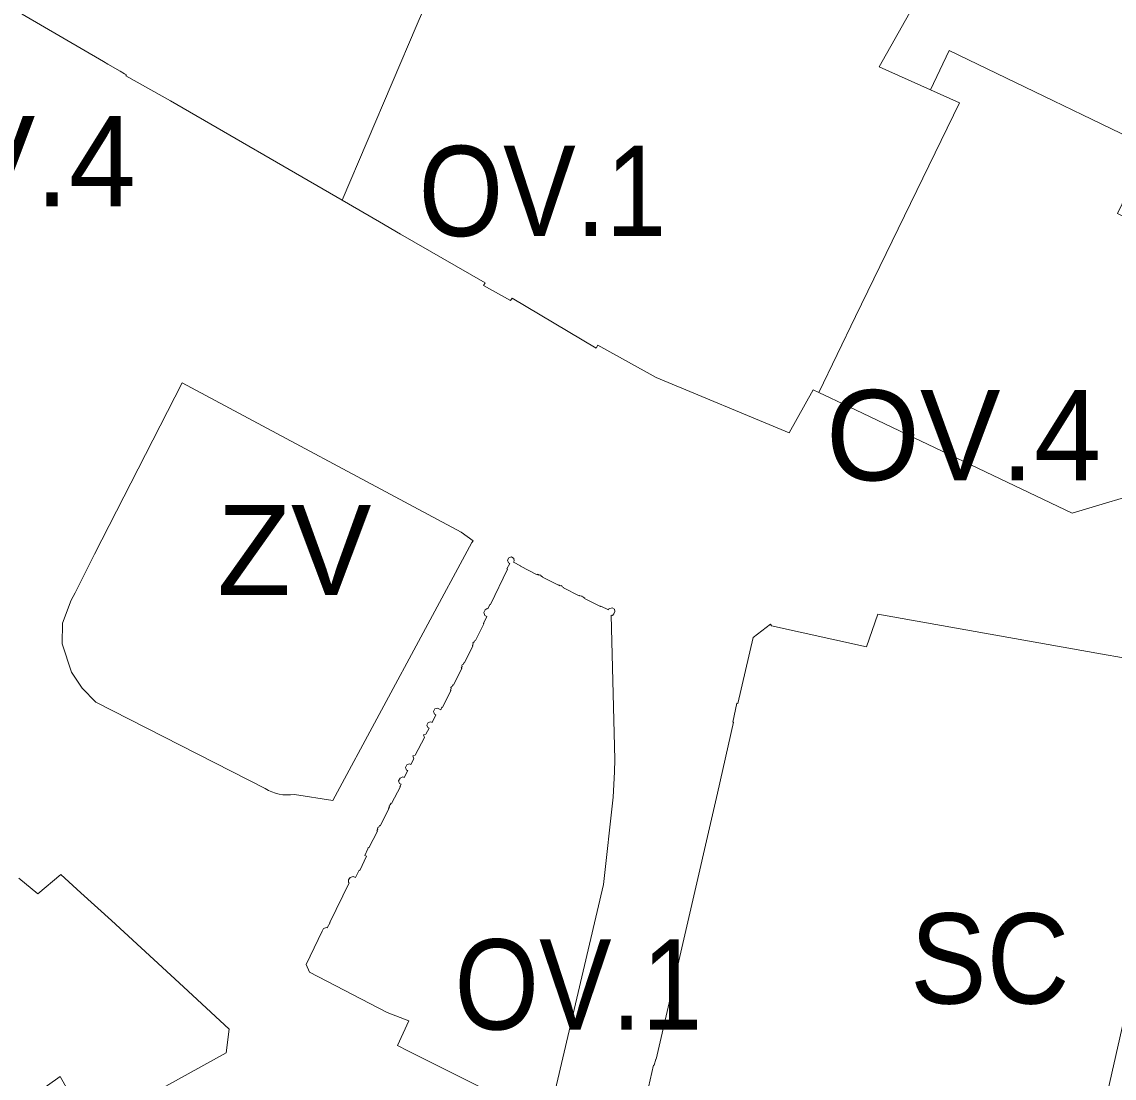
# Model space of a CAD drawing. Extents: x -650451 to -642268, y -1075216 to -1066610.
# Drawn here: x -647013.1 to -646868, y -1070712 to -1070571.6 of the extents above; entities that cross this region are included whole.
import ezdxf

# ---------------------------------------------------------------- set-up
doc = ezdxf.new("R2010")
doc.units = 0
doc.header["$LTSCALE"] = 4.8
for name, color, linetype, lineweight in [('11', 7, 'Continuous', 13), ('12', 7, 'Continuous', 13), ('15', 7, 'Continuous', 13), ('17', 7, 'Continuous', 13), ('40', 7, 'Continuous', 13)]:
    doc.layers.add(name, color=color, linetype=linetype, lineweight=lineweight)
doc.layers.add('62', color=7, linetype='Continuous')

msp = doc.modelspace()

# ---------------------------------------------------------------- linework, layer by layer
at = {"layer": '11'}
for points in [[(-646970.59, -1070595.31), (-646993.39, -1070582.12), (-646999.31, -1070578.78), (-646999.24, -1070578.67), (-646999.5, -1070578.52), (-647000.08, -1070578.18), (-647001.71, -1070577.23), (-647002.29, -1070576.9), (-647013.1, -1070570.62), (-647005.65, -1070557.68), (-647005.56, -1070557.72), (-647005.3, -1070557.33), (-646999.98, -1070548.21), (-646991.63, -1070534.15)], [(-646886.721, -1070555.37), (-646891.65, -1070564.15), (-646899.2, -1070577.61), (-646892.4, -1070580.64)], [(-646954.38, -1070557.43), (-646960.59, -1070571.95), (-646970.59, -1070595.31)], [(-646970.59, -1070595.31), (-646960.59, -1070571.95), (-646954.38, -1070557.43)], [(-646892.4, -1070580.64), (-646889.9, -1070575.41), (-646876.02, -1070582.12), (-646872.19, -1070583.97), (-646863.26, -1070588.3), (-646867.54, -1070597.11), (-646865.02, -1070598.34), (-646859.48, -1070601.1), (-646852.3, -1070604.63), (-646849.7, -1070605.93), (-646848.99, -1070606.28), (-646849.59, -1070607.4)], [(-646892.4, -1070580.64), (-646888.51, -1070582.38), (-646902.34, -1070610.8), (-646907.24, -1070620.87)], [(-646907.24, -1070620.87), (-646902.34, -1070610.8), (-646888.51, -1070582.38), (-646892.4, -1070580.64)], [(-646907.24, -1070620.87), (-646907.97, -1070620.52), (-646911.17, -1070626.24), (-646928.86, -1070618.91), (-646936.61, -1070614.62), (-646936.83, -1070615.01), (-646948, -1070608.33), (-646948.18, -1070608.65), (-646951.78, -1070606.66), (-646951.58, -1070606.31), (-646962.81, -1070599.83), (-646965.61, -1070598.2), (-646970.59, -1070595.31)], [(-646849.59, -1070607.4), (-646854.09, -1070615.86), (-646855.52, -1070618.54), (-646862.62, -1070633.65), (-646873.54, -1070636.92), (-646903.29, -1070622.75), (-646907.24, -1070620.87)], [(-646961.46, -1070670.34), (-646961.06, -1070669.57), (-646961.16, -1070669.2), (-646960.85, -1070669.1), (-646959.65, -1070666.76), (-646959.76, -1070666.41), (-646959.44, -1070666.32), (-646959.01, -1070665.52), (-646959.19, -1070665.43), (-646959.31, -1070665.1), (-646959.14, -1070664.75), (-646958.79, -1070664.66), (-646958.63, -1070664.74), (-646958.14, -1070663.73), (-646958.3, -1070663.65), (-646958.42, -1070663.31), (-646958.25, -1070662.96), (-646957.89, -1070662.84), (-646957.48, -1070663.05), (-646957.31, -1070662.71), (-646957.25, -1070662.74), (-646956.13, -1070660.48), (-646956.19, -1070660.45), (-646956.08, -1070660.22), (-646956.12, -1070660.12), (-646956.06, -1070660.01), (-646955.96, -1070659.97), (-646955.85, -1070659.76), (-646955.79, -1070659.79), (-646954.68, -1070657.55), (-646954.74, -1070657.52), (-646954.63, -1070657.29), (-646954.66, -1070657.19), (-646954.61, -1070657.08), (-646954.5, -1070657.04), (-646954.39, -1070656.81), (-646954.33, -1070656.84), (-646953.2, -1070654.57), (-646953.26, -1070654.53), (-646953.15, -1070654.31), (-646953.19, -1070654.2), (-646953.13, -1070654.09), (-646953.03, -1070654.06), (-646952.91, -1070653.83), (-646952.85, -1070653.87), (-646951.75, -1070651.64), (-646951.81, -1070651.6), (-646951.34, -1070650.65), (-646951.61, -1070650.52), (-646951.73, -1070650.14), (-646951.57, -1070649.76), (-646951.28, -1070649.62), (-646951.23, -1070649.65), (-646950.94, -1070649.06), (-646950.88, -1070649.09), (-646948.6, -1070644.37), (-646948.67, -1070644.34), (-646948.31, -1070643.61), (-646948.47, -1070643.54), (-646948.58, -1070643.18), (-646948.41, -1070642.85), (-646948.07, -1070642.74), (-646947.76, -1070642.97), (-646947.72, -1070643.27), (-646947.79, -1070643.45), (-646946.85, -1070643.93), (-646946.88, -1070643.99), (-646944.65, -1070645.11), (-646944.62, -1070645.05), (-646944.41, -1070645.15), (-646944.3, -1070645.12), (-646944.19, -1070645.17), (-646944.16, -1070645.28), (-646943.93, -1070645.39), (-646943.96, -1070645.45), (-646941.84, -1070646.52), (-646941.81, -1070646.46), (-646941.59, -1070646.57), (-646941.48, -1070646.53), (-646941.38, -1070646.59), (-646941.34, -1070646.7), (-646941.12, -1070646.81), (-646941.15, -1070646.87), (-646939.06, -1070647.92), (-646939.03, -1070647.86), (-646938.8, -1070647.98), (-646938.69, -1070647.94), (-646938.58, -1070648), (-646938.55, -1070648.1), (-646938.32, -1070648.22), (-646938.35, -1070648.28), (-646936.24, -1070649.34), (-646936.21, -1070649.28), (-646935.19, -1070649.79), (-646935.12, -1070649.63), (-646934.71, -1070649.53), (-646934.39, -1070649.68), (-646934.32, -1070650), (-646934.48, -1070650.33), (-646934.66, -1070650.55), (-646934.82, -1070650.48)], [(-646934.82, -1070650.48), (-646934.35, -1070669.69), (-646934.36, -1070671.33), (-646934.56, -1070674.69), (-646935.85, -1070686.31), (-646943.1, -1070717.25)], [(-646951.12, -1070713.75), (-646955.71, -1070711.45), (-646961.85, -1070708.38), (-646963.2, -1070707.7), (-646961.71, -1070704.43), (-646964.61, -1070703.3), (-646974.92, -1070697.94), (-646975.35, -1070696.93), (-646973.25, -1070692.48), (-646973.07, -1070692.12), (-646972.67, -1070691.99), (-646972.57, -1070692.04), (-646972.16, -1070691.35), (-646972.22, -1070691.32), (-646969.63, -1070686.07), (-646969.71, -1070686.03), (-646969.74, -1070685.68), (-646969.53, -1070685.37), (-646969.11, -1070685.22), (-646968.79, -1070685.37), (-646968.3, -1070684.38), (-646968.23, -1070684.41), (-646967.36, -1070682.51), (-646967.54, -1070682.42), (-646967.18, -1070681.53), (-646967.11, -1070681.38), (-646967.05, -1070681.42), (-646965.89, -1070679.18), (-646965.95, -1070679.15), (-646965.84, -1070678.92), (-646965.87, -1070678.82), (-646965.82, -1070678.71), (-646965.71, -1070678.67), (-646965.59, -1070678.44), (-646965.53, -1070678.48), (-646964.36, -1070676.21), (-646964.42, -1070676.18), (-646964.3, -1070675.96), (-646964.34, -1070675.85), (-646964.28, -1070675.74), (-646964.18, -1070675.71), (-646964.06, -1070675.49), (-646964, -1070675.52), (-646962.84, -1070673.28), (-646962.9, -1070673.25), (-646962.75, -1070672.95), (-646962.95, -1070672.85), (-646963.07, -1070672.49), (-646962.87, -1070672.15), (-646962.49, -1070671.99), (-646962.32, -1070672.07), (-646961.86, -1070671.15), (-646962.03, -1070671.07), (-646962.15, -1070670.72), (-646961.98, -1070670.37), (-646961.62, -1070670.26), (-646961.46, -1070670.34)]]:
    msp.add_lwpolyline(points, dxfattribs=at)
at = {"layer": '12'}
for points in [[(-646892.4, -1070580.64), (-646899.2, -1070577.61), (-646891.65, -1070564.15), (-646886.721, -1070555.37)], [(-646848.99, -1070606.28), (-646849.7, -1070605.93), (-646852.3, -1070604.63), (-646859.48, -1070601.1), (-646865.02, -1070598.34), (-646867.54, -1070597.11), (-646863.26, -1070588.3), (-646872.19, -1070583.97), (-646876.02, -1070582.12), (-646889.9, -1070575.41), (-646892.4, -1070580.64)]]:
    msp.add_lwpolyline(points, dxfattribs=at)
at = {"layer": '15'}
for points in [[(-646991.63, -1070534.15), (-646999.98, -1070548.21), (-647005.3, -1070557.33), (-647005.56, -1070557.72), (-647005.65, -1070557.68), (-647013.1, -1070570.62), (-647002.29, -1070576.9), (-647001.71, -1070577.23), (-647000.08, -1070578.18), (-646999.5, -1070578.52), (-646999.24, -1070578.67), (-646999.31, -1070578.78), (-646993.39, -1070582.12), (-646970.59, -1070595.31)], [(-646970.59, -1070595.31), (-646965.61, -1070598.2), (-646962.81, -1070599.83), (-646951.58, -1070606.31), (-646951.78, -1070606.66), (-646948.18, -1070608.65), (-646948, -1070608.33), (-646936.83, -1070615.01), (-646936.61, -1070614.62), (-646928.86, -1070618.91), (-646911.17, -1070626.24), (-646907.97, -1070620.52), (-646907.24, -1070620.87)], [(-646907.24, -1070620.87), (-646903.29, -1070622.75), (-646873.54, -1070636.92), (-646862.62, -1070633.65), (-646855.52, -1070618.54), (-646854.09, -1070615.86), (-646849.59, -1070607.4)], [(-646934.82, -1070650.48), (-646934.66, -1070650.55), (-646934.48, -1070650.33), (-646934.32, -1070650), (-646934.39, -1070649.68), (-646934.71, -1070649.53), (-646935.12, -1070649.63), (-646935.19, -1070649.79), (-646936.21, -1070649.28), (-646936.24, -1070649.34), (-646938.35, -1070648.28), (-646938.32, -1070648.22), (-646938.55, -1070648.1), (-646938.58, -1070648), (-646938.69, -1070647.94), (-646938.8, -1070647.98), (-646939.03, -1070647.86), (-646939.06, -1070647.92), (-646941.15, -1070646.87), (-646941.12, -1070646.81), (-646941.34, -1070646.7), (-646941.38, -1070646.59), (-646941.48, -1070646.53), (-646941.59, -1070646.57), (-646941.81, -1070646.46), (-646941.84, -1070646.52), (-646943.96, -1070645.45), (-646943.93, -1070645.39), (-646944.16, -1070645.28), (-646944.19, -1070645.17), (-646944.3, -1070645.12), (-646944.41, -1070645.15), (-646944.62, -1070645.05), (-646944.65, -1070645.11), (-646946.88, -1070643.99), (-646946.85, -1070643.93), (-646947.79, -1070643.45), (-646947.72, -1070643.27), (-646947.76, -1070642.97), (-646948.07, -1070642.74), (-646948.41, -1070642.85), (-646948.58, -1070643.18), (-646948.47, -1070643.54), (-646948.31, -1070643.61), (-646948.67, -1070644.34), (-646948.6, -1070644.37), (-646950.88, -1070649.09), (-646950.94, -1070649.06), (-646951.23, -1070649.65), (-646951.28, -1070649.62), (-646951.57, -1070649.76), (-646951.73, -1070650.14), (-646951.61, -1070650.52), (-646951.34, -1070650.65), (-646951.81, -1070651.6), (-646951.75, -1070651.64), (-646952.85, -1070653.87), (-646952.91, -1070653.83), (-646953.03, -1070654.06), (-646953.13, -1070654.09), (-646953.19, -1070654.2), (-646953.15, -1070654.31), (-646953.26, -1070654.53), (-646953.2, -1070654.57), (-646954.33, -1070656.84), (-646954.39, -1070656.81), (-646954.5, -1070657.04), (-646954.61, -1070657.08), (-646954.66, -1070657.19), (-646954.63, -1070657.29), (-646954.74, -1070657.52), (-646954.68, -1070657.55), (-646955.79, -1070659.79), (-646955.85, -1070659.76), (-646955.96, -1070659.97), (-646956.06, -1070660.01), (-646956.12, -1070660.12), (-646956.08, -1070660.22), (-646956.19, -1070660.45), (-646956.13, -1070660.48), (-646957.25, -1070662.74), (-646957.31, -1070662.71), (-646957.48, -1070663.05), (-646957.89, -1070662.84), (-646958.25, -1070662.96), (-646958.42, -1070663.31), (-646958.3, -1070663.65), (-646958.14, -1070663.73), (-646958.63, -1070664.74), (-646958.79, -1070664.66), (-646959.14, -1070664.75), (-646959.31, -1070665.1), (-646959.19, -1070665.43), (-646959.01, -1070665.52), (-646959.44, -1070666.32), (-646959.76, -1070666.41), (-646959.65, -1070666.76), (-646960.85, -1070669.1), (-646961.16, -1070669.2), (-646961.06, -1070669.57), (-646961.46, -1070670.34)], [(-646943.1, -1070717.25), (-646935.85, -1070686.31), (-646934.56, -1070674.69), (-646934.36, -1070671.33), (-646934.35, -1070669.69), (-646934.82, -1070650.48)], [(-646862.22, -1070656.94), (-646870.26, -1070655.52), (-646899.37, -1070650.34), (-646900.88, -1070654.68), (-646913.53, -1070651.9), (-646913.65, -1070651.7), (-646915.94, -1070653.44), (-646917.99, -1070662.22), (-646918.1, -1070662.19), (-646918.67, -1070664.7), (-646918.57, -1070664.73), (-646920.71, -1070674.14), (-646928.82, -1070709.51), (-646928.9, -1070709.49), (-646929.09, -1070710.32), (-646929.18, -1070710.3), (-646929.85, -1070713.22)], [(-646961.46, -1070670.34), (-646961.62, -1070670.26), (-646961.98, -1070670.37), (-646962.15, -1070670.72), (-646962.03, -1070671.07), (-646961.86, -1070671.15), (-646962.32, -1070672.07), (-646962.49, -1070671.99), (-646962.87, -1070672.15), (-646963.07, -1070672.49), (-646962.95, -1070672.85), (-646962.75, -1070672.95), (-646962.9, -1070673.25), (-646962.84, -1070673.28), (-646964, -1070675.52), (-646964.06, -1070675.49), (-646964.18, -1070675.71), (-646964.28, -1070675.74), (-646964.34, -1070675.85), (-646964.3, -1070675.96), (-646964.42, -1070676.18), (-646964.36, -1070676.21), (-646965.53, -1070678.48), (-646965.59, -1070678.44), (-646965.71, -1070678.67), (-646965.82, -1070678.71), (-646965.87, -1070678.82), (-646965.84, -1070678.92), (-646965.95, -1070679.15), (-646965.89, -1070679.18), (-646967.05, -1070681.42), (-646967.11, -1070681.38), (-646967.18, -1070681.53), (-646967.54, -1070682.42), (-646967.36, -1070682.51), (-646968.23, -1070684.41), (-646968.3, -1070684.38), (-646968.79, -1070685.37), (-646969.11, -1070685.22), (-646969.53, -1070685.37), (-646969.74, -1070685.68), (-646969.71, -1070686.03), (-646969.63, -1070686.07), (-646972.22, -1070691.32), (-646972.16, -1070691.35), (-646972.57, -1070692.04), (-646972.67, -1070691.99), (-646973.07, -1070692.12), (-646973.25, -1070692.48), (-646975.35, -1070696.93), (-646974.92, -1070697.94), (-646964.61, -1070703.3), (-646961.71, -1070704.43), (-646963.2, -1070707.7), (-646961.85, -1070708.38), (-646955.71, -1070711.45), (-646951.12, -1070713.75)], [(-647004.1, -1070718.67), (-646985.98, -1070708.66), (-646985.61, -1070705.54), (-646991.67, -1070699.91), (-647001.22, -1070691.06), (-647005.29, -1070687.4), (-647007.97, -1070684.96), (-647011.04, -1070687.54), (-647013.55, -1070685.46)], [(-646871.4, -1070725.07), (-646865.92, -1070700.98)], [(-647011.4, -1070714.21), (-647008.07, -1070711.83), (-647004.34, -1070718.44)]]:
    msp.add_lwpolyline(points, dxfattribs=at)
msp.add_lwpolyline([(-647006.53, -1070658.08), (-647005.14, -1070660.19), (-647003.29, -1070662.04), (-646980.82, -1070673.54), (-646980.381, -1070673.778), (-646979.919, -1070673.981), (-646979.438, -1070674.145), (-646978.942, -1070674.267), (-646978.439, -1070674.348), (-646977.932, -1070674.384), (-646977.427, -1070674.378), (-646976.93, -1070674.33), (-646971.8, -1070675.12), (-646953.32, -1070640.85), (-646953.16, -1070640.59), (-646954.74, -1070639.46), (-646991.83, -1070619.59), (-646994.77, -1070625.34), (-647003.47, -1070642.4), (-647006.08, -1070647.54), (-647006.57, -1070648.51), (-647007.74, -1070651.54), (-647007.78, -1070654.28)], close=True, dxfattribs=at)
at = {"layer": '17'}
for points in [[(-646929.85, -1070713.22), (-646929.18, -1070710.3), (-646929.09, -1070710.32), (-646928.9, -1070709.49), (-646928.82, -1070709.51), (-646920.71, -1070674.14), (-646918.57, -1070664.73), (-646918.67, -1070664.7), (-646918.1, -1070662.19), (-646917.99, -1070662.22), (-646915.94, -1070653.44), (-646913.65, -1070651.7), (-646913.53, -1070651.9), (-646900.88, -1070654.68), (-646899.37, -1070650.34), (-646870.26, -1070655.52), (-646862.22, -1070656.94)], [(-647013.55, -1070685.46), (-647011.04, -1070687.54), (-647007.97, -1070684.96), (-647005.29, -1070687.4), (-647001.22, -1070691.06), (-646991.67, -1070699.91), (-646985.61, -1070705.54), (-646985.98, -1070708.66), (-647004.1, -1070718.67)], [(-646865.92, -1070700.98), (-646871.4, -1070725.07)], [(-647004.34, -1070718.44), (-647008.07, -1070711.83), (-647011.4, -1070714.21)]]:
    msp.add_lwpolyline(points, dxfattribs=at)
at = {"layer": '40'}
msp.add_lwpolyline([(-647006.53, -1070658.08), (-647007.78, -1070654.28), (-647007.74, -1070651.54), (-647006.57, -1070648.51), (-647006.08, -1070647.54), (-647003.47, -1070642.4), (-646994.77, -1070625.34), (-646991.83, -1070619.59), (-646954.74, -1070639.46), (-646953.16, -1070640.59), (-646953.32, -1070640.85), (-646971.8, -1070675.12), (-646976.93, -1070674.33), (-646977.427, -1070674.378), (-646977.932, -1070674.384), (-646978.439, -1070674.348), (-646978.942, -1070674.267), (-646979.438, -1070674.145), (-646979.919, -1070673.981), (-646980.381, -1070673.778), (-646980.82, -1070673.54), (-647003.29, -1070662.04), (-647005.14, -1070660.19)], close=True, dxfattribs=at)

# ---------------------------------------------------------------- texts
at = {"layer": '62'}
for s, p in [('OV.4', (-647034.557, -1070596.157)), ('OV.4', (-646906.263, -1070632.567)), ('ZV', (-646987.186, -1070647.829))]:
    msp.add_text(s, height=12, dxfattribs=at).set_placement(p)
for s, width, p in [('OV.1', 0.9, (-646960.407, -1070600.099)), ('SC', 0.95, (-646895.096, -1070702.12)), ('OV.1', 0.9, (-646955.64, -1070705.567))]:
    msp.add_text(s, height=12, dxfattribs=dict(at, width=width)).set_placement(p)

doc.saveas('drawing.dxf')
